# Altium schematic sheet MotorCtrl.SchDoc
size A3; Revision: C.2
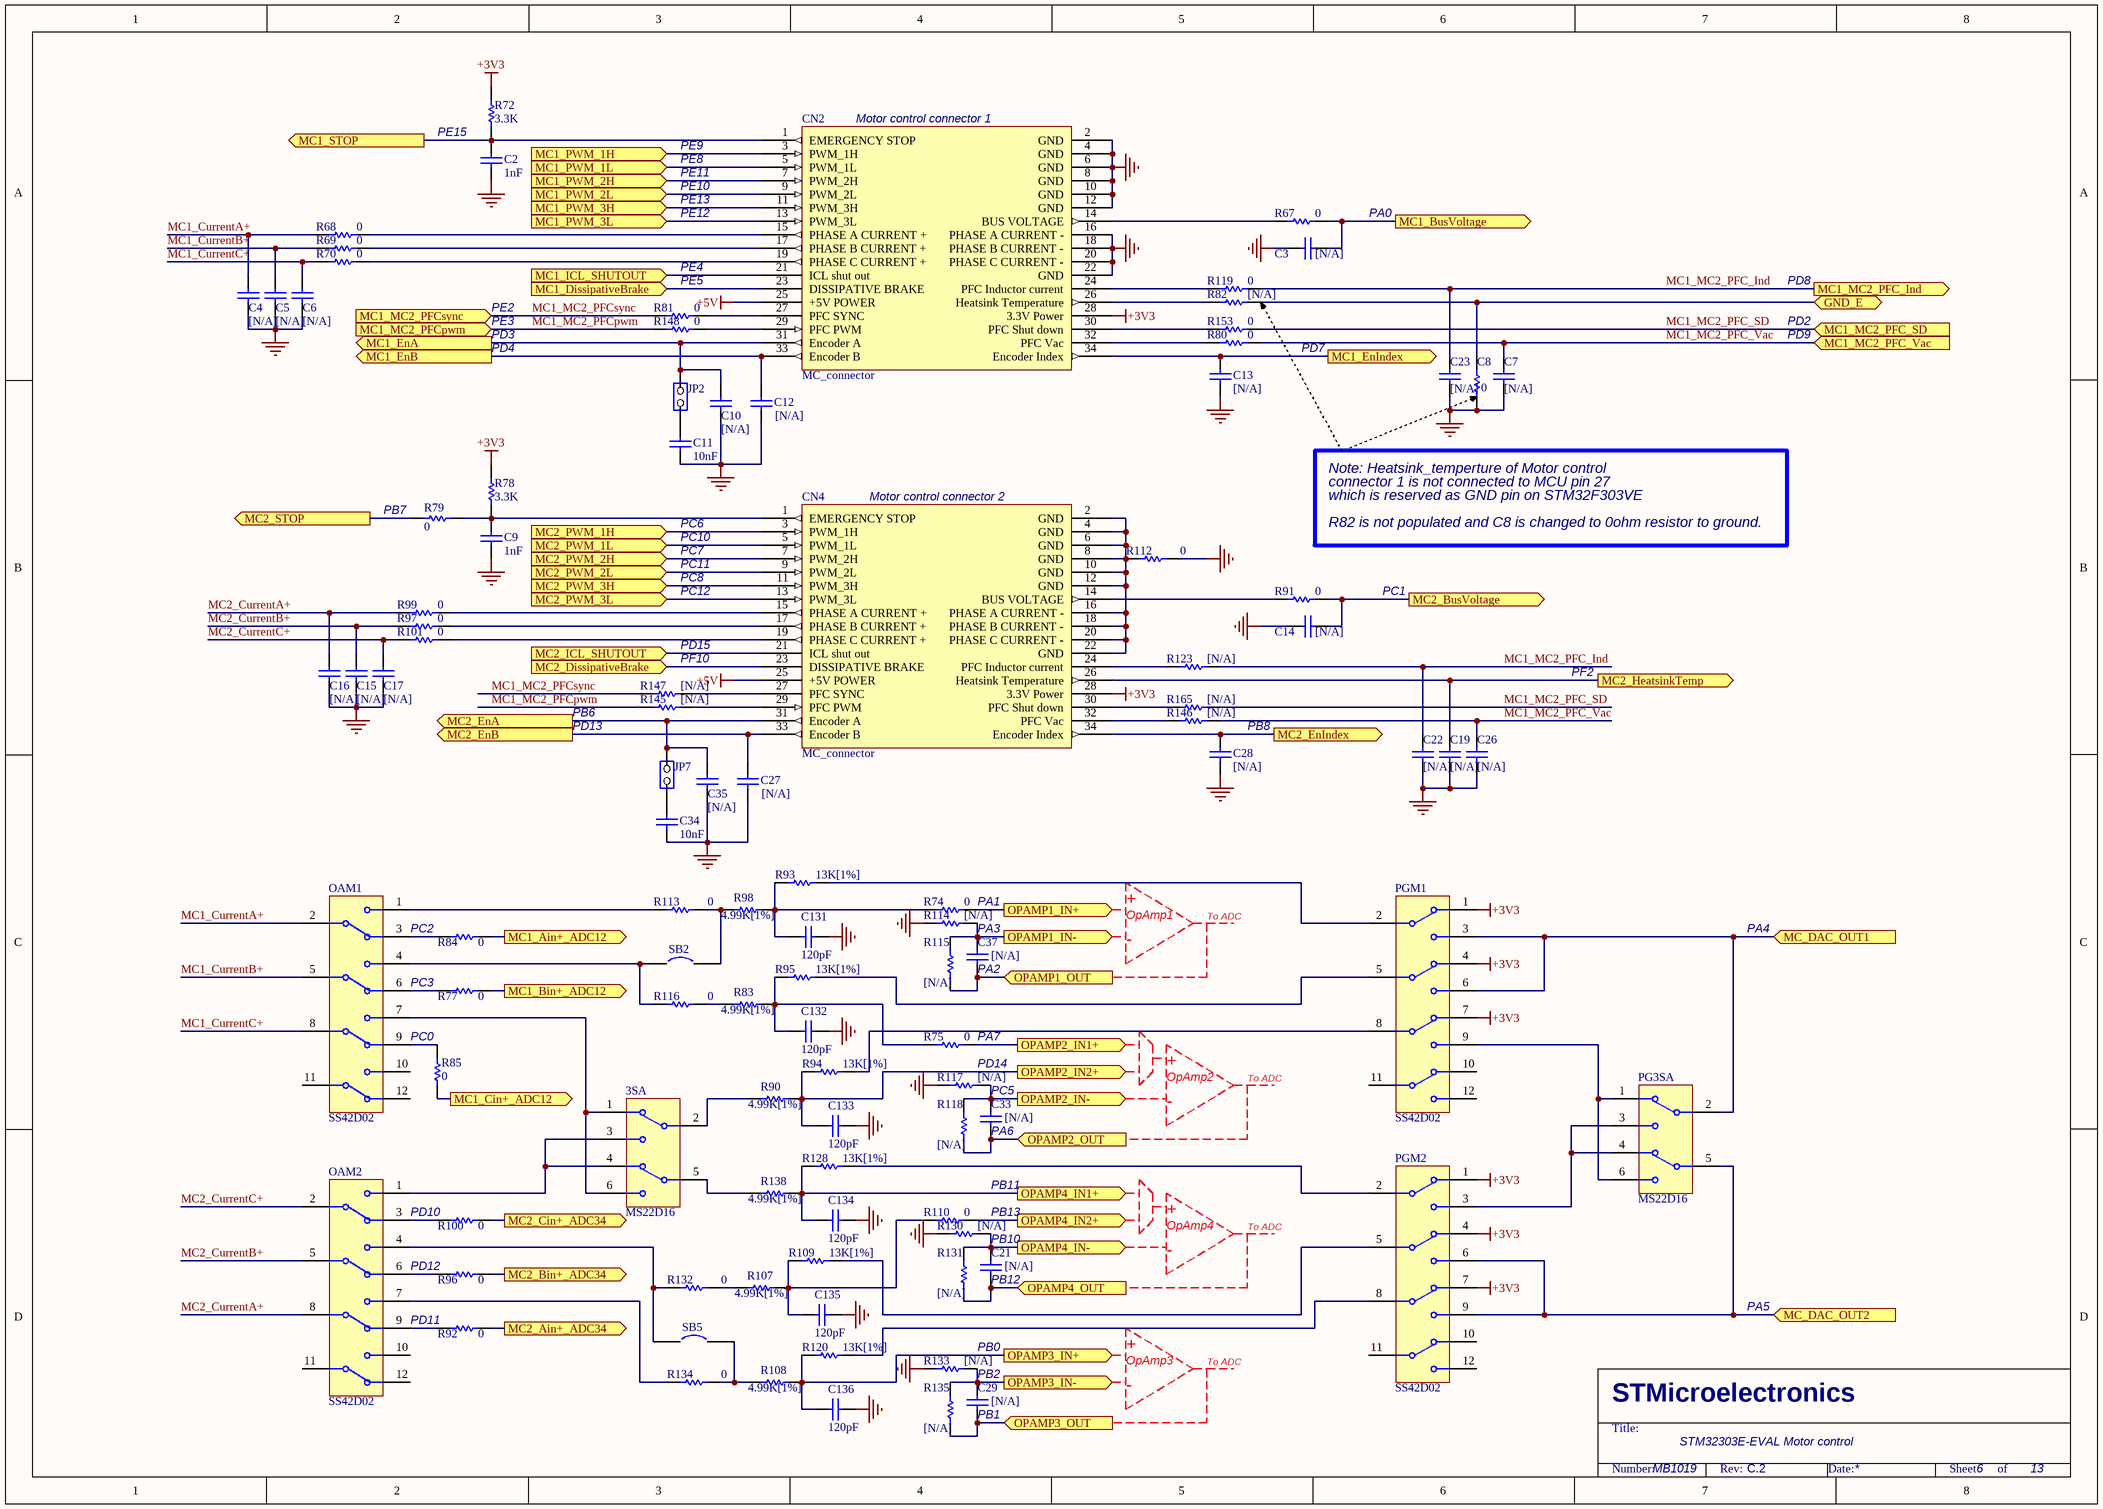
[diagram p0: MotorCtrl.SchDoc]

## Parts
3SA  MS22D16  [MS22D16]
C2  1nF  [0603C]
C3  [N/A]  [0603C]
C4  [N/A]  [0603C]
C5  [N/A]  [0603C]
C6  [N/A]  [0603C]
C7  [N/A]  [0603C]
C8  0  [0603R]
C9  1nF  [0603C]
C10  [N/A]  [0603C]
C11  10nF  [0603C]
C12  [N/A]  [0603C]
C13  [N/A]  [0603C]
C14  [N/A]  [0603C]
C15  [N/A]  [0603C]
C16  [N/A]  [0603C]
C17  [N/A]  [0603C]
C19  [N/A]  [0603C]
C21  [N/A]  [0603C]
C22  [N/A]  [0603C]
C23  [N/A]  [0603C]
C26  [N/A]  [0603C]
C27  [N/A]  [0603C]
C28  [N/A]  [0603C]
C29  [N/A]  [0603C]
C33  [N/A]  [0603C]
C34  10nF  [0603C]
C35  [N/A]  [0603C]
C37  [N/A]  [0603C]
C131  120pF  [0603C]
C132  120pF  [0603C]
C133  120pF  [0603C]
C134  120pF  [0603C]
C135  120pF  [0603C]
C136  120pF  [0603C]
CN2  MC_connector  [IDC34S]
CN4  MC_connector  [IDC34S]
JP2  (no value)  [SIP2]
JP7  (no value)  [SIP2]
OAM1  SS42D02  [SS42D02]
OAM2  SS42D02  [SS42D02]
PG3SA  MS22D16  [MS22D16]
PGM1  SS42D02  [SS42D02]
PGM2  SS42D02  [SS42D02]
R67  0  [0603R]
R68  0  [0603R]
R69  0  [0603R]
R70  0  [0603R]
R72  3.3K  [0603R]
R74  0  [0603R]
R75  0  [0603R]
R77  0  [0603R]
R78  3.3K  [0603R]
R79  0  [0603R]
R80  0  [0603R]
R81  0  [0603R]
R82  [N/A]  [0603R]
R83  4.99K[1%]  [0603R]
R84  0  [0603R]
R85  0  [0603R]
R90  4.99K[1%]  [0603R]
R91  0  [0603R]
R92  0  [0603R]
R93  13K[1%]  [0603R]
R94  13K[1%]  [0603R]
R95  13K[1%]  [0603R]
R96  0  [0603R]
R97  0  [0603R]
R98  4.99K[1%]  [0603R]
R99  0  [0603R]
R100  0  [0603R]
R101  0  [0603R]
R107  4.99K[1%]  [0603R]
R108  4.99K[1%]  [0603R]
R109  13K[1%]  [0603R]
R110  0  [0603R]
R112  0  [0603R]
R113  0  [0603R]
R114  [N/A]  [0603R]
R115  [N/A]  [0603R]
R116  0  [0603R]
R117  [N/A]  [0603R]
R118  [N/A]  [0603R]
R119  0  [0603R]
R120  13K[1%]  [0603R]
R123  [N/A]  [0603R]
R128  13K[1%]  [0603R]
R130  [N/A]  [0603R]
R131  [N/A]  [0603R]
R132  0  [0603R]
R133  [N/A]  [0603R]
R134  0  [0603R]
R135  [N/A]  [0603R]
R138  4.99K[1%]  [0603R]
R145  [N/A]  [0603R]
R146  [N/A]  [0603R]
R147  [N/A]  [0603R]
R148  0  [0603R]
R153  0  [0603R]
R165  [N/A]  [0603R]
SB2  (no value)  [JP2_SMD]
SB5  (no value)  [JP2_SMD]

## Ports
GND_E (bidir), MC1_Ain+_ADC12 (out), MC1_Bin+_ADC12 (out), MC1_BusVoltage (out), MC1_Cin+_ADC12 (out), MC1_DissipativeBrake (in), MC1_EnA (out), MC1_EnB (out), MC1_EnIndex (out), MC1_ICL_SHUTOUT (in), MC1_MC2_PFC_Ind (out), MC1_MC2_PFC_SD (in), MC1_MC2_PFC_Vac (in), MC1_MC2_PFCpwm (in), MC1_MC2_PFCsync (in), MC1_PWM_1H (in), MC1_PWM_1L (in), MC1_PWM_2H (in), MC1_PWM_2L (in), MC1_PWM_3H (in), MC1_PWM_3L (in), MC1_STOP (out), MC2_Ain+_ADC34 (out), MC2_Bin+_ADC34 (out), MC2_BusVoltage (out), MC2_Cin+_ADC34 (out), MC2_DissipativeBrake (in), MC2_EnA (out), MC2_EnB (out), MC2_EnIndex (out), MC2_HeatsinkTemp (out), MC2_ICL_SHUTOUT (in), MC2_PWM_1H (in), MC2_PWM_1L (in), MC2_PWM_2H (in), MC2_PWM_2L (in), MC2_PWM_3H (in), MC2_PWM_3L (in), MC2_STOP (out), MC_DAC_OUT1 (in), MC_DAC_OUT2 (in), OPAMP1_IN+ (out), OPAMP1_IN- (out), OPAMP1_OUT (in), OPAMP2_IN1+ (out), OPAMP2_IN2+ (out), OPAMP2_IN- (out), OPAMP2_OUT (in), OPAMP3_IN+ (out), OPAMP3_IN- (out), OPAMP3_OUT (in), OPAMP4_IN1+ (out), OPAMP4_IN2+ (out), OPAMP4_IN- (out), OPAMP4_OUT (in)

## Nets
+3V3: CN2.28(3.3V_Power) CN4.28(3.3V_Power) PGM1.1 PGM1.4 PGM1.7 PGM2.1 PGM2.4 PGM2.7 R72.2 R78.2
+5V: CN2.25(+5V_POWER) CN4.25(+5V_POWER)
GND: C2.1 C3.2 C4.1 C5.1 C6.1 C7.1 C8.2 C9.1 C10.1 C11.1 C12.1 C13.1 C14.2 C15.1 C16.1 C17.1 C19.1 C22.1 C23.1 C26.1 C27.1 C28.1 C34.1 C35.1 C131.2 C132.2 C133.2 C134.2 C135.2 C136.2 CN2.2(GND) CN2.4(GND) CN2.6(GND) CN2.8(GND) CN2.10(GND) CN2.12(GND) CN2.16(PHASE_A_CURRENT_-) CN2.18(PHASE_B_CURRENT_-) CN2.20(PHASE_C_CURRENT_-) CN2.22(GND) R112.1 R114.1 R117.1 R130.1 R133.1
GND_E: C8.1 R82.2 ; port GND_E
MC1_Ain+_ADC12: R84.1 ; port MC1_Ain+_ADC12
MC1_Bin+_ADC12: R77.1 ; port MC1_Bin+_ADC12
MC1_BusVoltage: C3.1 R67.1 ; port MC1_BusVoltage
MC1_Cin+_ADC12: R85.2 ; port MC1_Cin+_ADC12
MC1_CurrentA+: C4.2 OAM1.2 R68.2
MC1_CurrentB+: C5.2 OAM1.5 R69.2
MC1_CurrentC+: C6.2 OAM1.8 R70.2
MC1_DissipativeBrake: CN2.23(DISSIPATIVE_BRAKE) ; port MC1_DissipativeBrake
MC1_EnA: C10.2 CN2.31(Encoder_A) JP2.1(COMMON) ; port MC1_EnA
MC1_EnB: C12.2 CN2.33(Encoder_B) ; port MC1_EnB
MC1_EnIndex: C13.2 CN2.34(Encoder_Index) ; port MC1_EnIndex
MC1_ICL_SHUTOUT: CN2.21(ICL_shut_out) ; port MC1_ICL_SHUTOUT
MC1_MC2_PFC_Ind: C22.2 C23.2 R119.1 R123.1 ; port MC1_MC2_PFC_Ind
MC1_MC2_PFC_SD: R153.1 R165.1 ; port MC1_MC2_PFC_SD
MC1_MC2_PFC_Vac: C7.2 C26.2 R80.1 R146.1 ; port MC1_MC2_PFC_Vac
MC1_MC2_PFCpwm: R145.2 R148.2 ; port MC1_MC2_PFCpwm
MC1_MC2_PFCsync: R81.2 R147.2 ; port MC1_MC2_PFCsync
MC1_PWM_1H: CN2.3(PWM_1H) ; port MC1_PWM_1H
MC1_PWM_1L: CN2.5(PWM_1L) ; port MC1_PWM_1L
MC1_PWM_2H: CN2.7(PWM_2H) ; port MC1_PWM_2H
MC1_PWM_2L: CN2.9(PWM_2L) ; port MC1_PWM_2L
MC1_PWM_3H: CN2.11(PWM_3H) ; port MC1_PWM_3H
MC1_PWM_3L: CN2.13(PWM_3L) ; port MC1_PWM_3L
MC1_STOP: C2.2 CN2.1(EMERGENCY_STOP) R72.1 ; port MC1_STOP
MC2_Ain+_ADC34: R92.1 ; port MC2_Ain+_ADC34
MC2_Bin+_ADC34: R96.1 ; port MC2_Bin+_ADC34
MC2_BusVoltage: C14.1 R91.1 ; port MC2_BusVoltage
MC2_Cin+_ADC34: R100.1 ; port MC2_Cin+_ADC34
MC2_CurrentA+: C16.2 OAM2.8 R99.2
MC2_CurrentB+: C15.2 OAM2.5 R97.2
MC2_CurrentC+: C17.2 OAM2.2 R101.2
MC2_DissipativeBrake: CN4.23(DISSIPATIVE_BRAKE) ; port MC2_DissipativeBrake
MC2_EnA: C35.2 CN4.31(Encoder_A) JP7.1(COMMON) ; port MC2_EnA
MC2_EnB: C27.2 CN4.33(Encoder_B) ; port MC2_EnB
MC2_EnIndex: C28.2 CN4.34(Encoder_Index) ; port MC2_EnIndex
MC2_HeatsinkTemp: C19.2 CN4.26(Heatsink_Temperature) ; port MC2_HeatsinkTemp
MC2_ICL_SHUTOUT: CN4.21(ICL_shut_out) ; port MC2_ICL_SHUTOUT
MC2_PWM_1H: CN4.3(PWM_1H) ; port MC2_PWM_1H
MC2_PWM_1L: CN4.5(PWM_1L) ; port MC2_PWM_1L
MC2_PWM_2H: CN4.7(PWM_2H) ; port MC2_PWM_2H
MC2_PWM_2L: CN4.9(PWM_2L) ; port MC2_PWM_2L
MC2_PWM_3H: CN4.11(PWM_3H) ; port MC2_PWM_3H
MC2_PWM_3L: CN4.13(PWM_3L) ; port MC2_PWM_3L
MC2_STOP: R79.2 ; port MC2_STOP
MC_DAC_OUT1: PG3SA.2 PGM1.3 PGM1.6 ; port MC_DAC_OUT1
MC_DAC_OUT2: PG3SA.5 PGM2.6 PGM2.9 ; port MC_DAC_OUT2
OPAMP1_IN+: R74.1 ; port OPAMP1_IN+
OPAMP1_IN-: C37.2 R114.2 R115.2 ; port OPAMP1_IN-
OPAMP1_OUT: C37.1 R115.1 ; port OPAMP1_OUT
OPAMP2_IN1+: R75.1 ; port OPAMP2_IN1+
OPAMP2_IN2+: C133.1 R90.2 R94.1 ; port OPAMP2_IN2+
OPAMP2_IN-: C33.2 R117.2 R118.2 ; port OPAMP2_IN-
OPAMP2_OUT: C33.1 R118.1 ; port OPAMP2_OUT
OPAMP3_IN+: C136.1 R108.2 R120.1 ; port OPAMP3_IN+
OPAMP3_IN-: C29.2 R133.2 R135.2 ; port OPAMP3_IN-
OPAMP3_OUT: C29.1 R135.1 ; port OPAMP3_OUT
OPAMP4_IN1+: C134.1 R128.1 R138.2 ; port OPAMP4_IN1+
OPAMP4_IN2+: R110.1 ; port OPAMP4_IN2+
OPAMP4_IN-: C21.2 R130.2 R131.2 ; port OPAMP4_IN-
OPAMP4_OUT: C21.1 R131.1 ; port OPAMP4_OUT
Net3SA_1: 3SA.1 3SA.6 OAM1.7
Net3SA_2: 3SA.2 R90.1
Net3SA_3: 3SA.3 3SA.4 OAM2.1
Net3SA_5: 3SA.5 R138.1
NetC9_2: C9.2 CN4.1(EMERGENCY_STOP) R78.1 R79.1
NetC11_2: C11.2 JP2.2(NO)
NetC34_2: C34.2 JP7.2(NO)
NetC131_1: C131.1 R74.2 R93.1 R98.2
NetC132_1: C132.1 R75.2 R83.2 R95.1
NetC135_1: C135.1 R107.2 R109.1 R110.2
NetCN2_14: CN2.14(BUS_VOLTAGE) R67.2
NetCN2_15: CN2.15(PHASE_A_CURRENT_+) R68.1
NetCN2_17: CN2.17(PHASE_B_CURRENT_+) R69.1
NetCN2_19: CN2.19(PHASE_C_CURRENT_+) R70.1
NetCN2_24: CN2.24(PFC_Inductor_current) R119.2
NetCN2_26: CN2.26(Heatsink_Temperature) R82.1
NetCN2_27: CN2.27(PFC_SYNC) R81.1
NetCN2_29: CN2.29(PFC_PWM) R148.1
NetCN2_30: CN2.30(PFC_Shut_down) R153.2
NetCN2_32: CN2.32(PFC_Vac) R80.2
NetCN4_2: CN4.2(GND) CN4.4(GND) CN4.6(GND) CN4.8(GND) CN4.10(GND) CN4.12(GND) CN4.16(PHASE_A_CURRENT_-) CN4.18(PHASE_B_CURRENT_-) CN4.20(PHASE_C_CURRENT_-) CN4.22(GND) R112.2
NetCN4_14: CN4.14(BUS_VOLTAGE) R91.2
NetCN4_15: CN4.15(PHASE_A_CURRENT_+) R99.1
NetCN4_17: CN4.17(PHASE_B_CURRENT_+) R97.1
NetCN4_19: CN4.19(PHASE_C_CURRENT_+) R101.1
NetCN4_24: CN4.24(PFC_Inductor_current) R123.2
NetCN4_27: CN4.27(PFC_SYNC) R147.1
NetCN4_29: CN4.29(PFC_PWM) R145.1
NetCN4_30: CN4.30(PFC_Shut_down) R165.2
NetCN4_32: CN4.32(PFC_Vac) R146.2
NetOAM1_1: OAM1.1 R113.2
NetOAM1_3: OAM1.3 R84.2
NetOAM1_4: OAM1.4 R116.2 SB2.1
NetOAM1_6: OAM1.6 R77.2
NetOAM1_9: OAM1.9 R85.1
NetOAM2_3: OAM2.3 R100.2
NetOAM2_4: OAM2.4 R132.2 SB5.1
NetOAM2_6: OAM2.6 R96.2
NetOAM2_7: OAM2.7 R134.2
NetOAM2_9: OAM2.9 R92.2
NetPG3SA_1: PG3SA.1 PG3SA.6 PGM1.9
NetPG3SA_3: PG3SA.3 PG3SA.4 PGM2.3
NetPGM1_2: PGM1.2 R93.2
NetPGM1_5: PGM1.5 R95.2
NetPGM1_8: PGM1.8 R94.2
NetPGM2_2: PGM2.2 R128.2
NetPGM2_5: PGM2.5 R109.2
NetPGM2_8: PGM2.8 R120.2
NetR83_1: R83.1 R116.1
NetR98_1: R98.1 R113.1 SB2.2
NetR107_1: R107.1 R132.1
NetR108_1: R108.1 R134.1 SB5.2

Not connected (* = marked no-connect by the designer): OAM1 10 11 12; OAM2 10 11 12; PGM1 10 11 12; PGM2 10 11 12

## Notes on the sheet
- PE15
- PE9
- PE8
- PE11
- (near CN2) Motor control connector 1
- PE10
- PE13
- PE12
- PA0
- PE2
- PE5
- PE4
- PD8
- PD3
- PD4
- PE3
- PD7
- PD2
- PD9
- (near R79) PB7
- (near CN4) Motor control connector 2
- Note: Heatsink_temperture of Motor control
- which is reserved as GND pin on STM32F303VE
- connector 1 is not connected to MCU pin 27
- PC6
- PC10
- PC7
- PC11
- PC8
- R82 is not populated and C8 is changed to 0ohm resistor to ground.
- PC12
- PD15
- PC1
- PB6
- PF10
- PF2
- PD13
- PB8
- PA1
- +
- OpAmp1
- To ADC
- PC2
- PC3
- PA3
- (near C37) PA2
- -
- PA4
- PC0
- (near R75) PA7
- PD14
- PC5
- OpAmp2
- (near C33) PA6
- PB11
- PD10
- PB13
- PB10
- OpAmp4
- PD12
- PD11
- (near C21) PB12
- PA5
- (near R133) PB0
- PB2
- OpAmp3
- (near C29) PB1
- STM32303E-EVAL Motor control
- MB1019
- 6
- 13

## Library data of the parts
3SA PG3SA = MS22D16: DPDT; Revision 1: Jul-2002: Re-released for DXP Platform.; Revision 2: 17-Dec-2003: Schematic revised, PCB Footprint replaced.
C2 C9 = CAP: Capacitor; Value: 100pF
C3-C7 C10-C17 C19 C21-C23 C26-C29 C33-C35 C37 C131-C136 = cap: Capacitor; Value: 100pF
C8 R67-R70 R72 R74 R75 R77-R85 R90-R101 R107-R110 R112-R120 R123 R128 R130-R135 R138 R145-R148 R153 R165 = Res1: Resistor; Value: 1K
CN2 CN4 = MC_connector_1
JP2 JP7 = JP2
OAM1 OAM2 = SS42D02_1: SPDT Subminiature Toggle Switch, Right Angle Mounting, Vertical Actuation; Revision 1: Jul-2002: Re-released for DXP Platform.; Revision 2: 17-Dec-2003: Schematic revised, PCB Footprint replaced.
PGM1 PGM2 = SS42D02: SPDT Subminiature Toggle Switch, Right Angle Mounting, Vertical Actuation; Revision 1: Jul-2002: Re-released for DXP Platform.; Revision 2: 17-Dec-2003: Schematic revised, PCB Footprint replaced.
SB2 SB5 = Circuit Breaker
